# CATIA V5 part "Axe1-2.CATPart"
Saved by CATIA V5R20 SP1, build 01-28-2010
Part number: Axe1-2
Bounding box of the stored display mesh (mm): x 59.917 to 140.207, y 172.86 to 189.495, z -378.197 to -363.573
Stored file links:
  C:\Users\RENARD Simon\Documents\Cours IFMA\2ème année\IAO\Axe1-2.CATPart
  C:\Users\RENARD Simon\Documents\Cours IFMA\2ème année\IAO\Trainattero.CATProduct
  C:\Users\RENARD Simon\Documents\Cours IFMA\2ème année\IAO\Piece1.CATPart
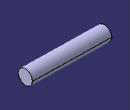
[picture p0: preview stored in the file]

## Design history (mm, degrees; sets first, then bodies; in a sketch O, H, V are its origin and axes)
Set1
  DatumSurface1: linked copy from another document
  Line1: linked copy from another document
  Plane1: linked copy from another document
Body1 (main body)
  Sketch1 on face of DatumSurface1, origin (136.303, -2.7915, 0), H (-0.0205, -0.9998, 0), V (0, 0, 1)
    circle A1 centre (-183.1883, -370.8854) radius 7.5
    point P1 (-183.1883, -370.8854)
    reference projected point E1 (-183.1883, -370.8854) from Line1
    radius A1 = 7.5
    coincidence: E1 P1
  Pad1: profile Sketch1, direction (-0.9998, 0.0205, 0), length 80
  Plane2: type Offset, RefPlane Plane1, Offset 40, reversed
